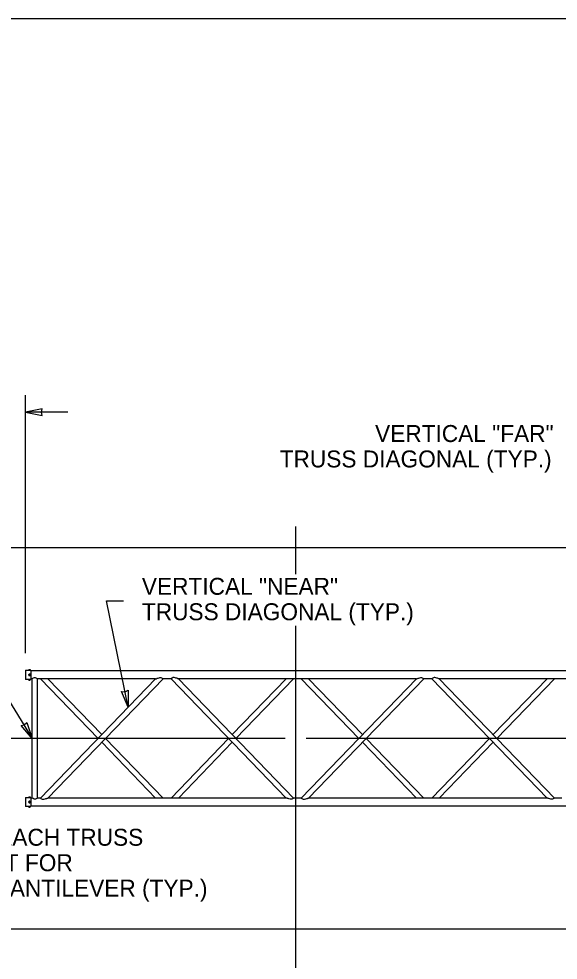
# Model space of a CAD drawing. Extents: x 99862 to 104211, y 98939 to 111076.
# Drawn here: x 100432 to 100941, y 104187 to 105075 of the extents above; entities that cross this region are included whole.
import ezdxf

# ---------------------------------------------------------------- set-up
doc = ezdxf.new("R2010")
doc.units = 0
for name, color, linetype in [('Level 15', 7, 'Continuous'), ('Level 20', 7, 'Continuous'), ('Level 6', 7, 'Continuous'), ('Level 60', 7, 'Continuous'), ('Level 62', 7, 'Continuous'), ('Level 9', 7, 'Continuous')]:
    doc.layers.add(name, color=color, linetype=linetype)

msp = doc.modelspace()

# ---------------------------------------------------------------- linework, layer by layer
at = {"layer": 'Level 15'}
for p, q in [((100438.11, 104476.27), (100438.11, 104719.89)), ((100478.11, 104703.89), (100438.11, 104703.89)), ((100301.12, 104629.04), (100444.36, 104395.89)), ((100693.11, 104595.89), (100693.11, 104550.99)), ((100534.96, 104425.29), (100514.64, 104525.79)), ((100514.64, 104525.79), (100530.64, 104525.79)), ((100693.11, 104502.01), (100693.11, 103988.28)), ((100683.11, 104395.89), (100213.11, 104395.89)), ((101294.5, 104395.89), (100703.11, 104395.89))]:
    msp.add_line(p, q, dxfattribs=at)
for points in [[(100438.11, 104703.89), (100453.84, 104700.81), (100453.11, 104703.89), (100453.84, 104706.98)], [(100534.96, 104425.29), (100528.82, 104440.09), (100531.99, 104439.99), (100534.87, 104441.32)], [(100444.36, 104395.89), (100433.83, 104407.97), (100436.87, 104408.88), (100439.17, 104411.05)]]:
    msp.add_lwpolyline(points, close=True, dxfattribs=at)
at = {"layer": 'Level 20'}
for p, q in [((100506.53, 104395.89), (100452.13, 104452.14)), ((100510.01, 104399.49), (100459.09, 104452.14)), ((100633.32, 104399.49), (100684.24, 104452.14)), ((100636.8, 104395.89), (100691.2, 104452.14)), ((100752.77, 104395.89), (100698.37, 104452.14)), ((100756.25, 104399.49), (100705.33, 104452.14)), ((100879.56, 104399.49), (100930.48, 104452.14)), ((100883.04, 104395.89), (100937.44, 104452.14)), ((100560.93, 104339.64), (100510.01, 104392.3)), ((100567.88, 104339.64), (100513.49, 104395.89)), ((100575.45, 104339.64), (100629.85, 104395.89)), ((100582.4, 104339.64), (100633.32, 104392.3)), ((100807.17, 104339.64), (100756.25, 104392.3)), ((100814.12, 104339.64), (100759.72, 104395.89)), ((100821.69, 104339.64), (100876.08, 104395.89)), ((100828.64, 104339.64), (100879.56, 104392.3))]:
    msp.add_line(p, q, dxfattribs=at)
at = {"layer": 'Level 6'}
for p, q in [((100985.61, 104575.89), (100400.61, 104575.89)), ((100438.11, 104460.27), (100438.11, 104451.52)), ((100438.11, 104460.27), (100441.16, 104460.27)), ((100442.57, 104460.27), (100443.11, 104460.27)), ((100443.11, 104460.27), (100443.11, 104451.52)), ((101326.12, 104459.64), (100443.11, 104459.64)), ((100441.16, 104451.52), (100438.11, 104451.52)), ((100443.11, 104451.52), (100442.57, 104451.52)), ((100444.36, 104452.14), (100443.11, 104452.14)), ((100444.36, 104339.64), (100444.36, 104452.14)), ((100449.36, 104339.64), (100449.36, 104452.14)), ((100560.93, 104452.14), (100449.36, 104452.14)), ((100449.36, 104339.64), (100449.36, 104452.13)), ((100560.93, 104452.14), (100452.13, 104339.64)), ((100567.88, 104452.14), (100459.09, 104339.64)), ((100575.45, 104452.14), (100567.88, 104452.14)), ((100575.45, 104452.14), (100684.24, 104339.64)), ((100582.4, 104452.14), (100691.2, 104339.64)), ((100807.17, 104452.14), (100582.4, 104452.14)), ((100807.17, 104452.14), (100698.37, 104339.64)), ((100814.12, 104452.14), (100705.33, 104339.64)), ((100821.69, 104452.14), (100814.12, 104452.14)), ((100821.69, 104452.14), (100930.48, 104339.64)), ((100828.64, 104452.14), (100937.44, 104339.64)), ((101053.4, 104452.14), (100828.64, 104452.14)), ((100438.11, 104340.27), (100438.11, 104331.52)), ((100438.11, 104340.27), (100441.16, 104340.27)), ((100442.57, 104340.27), (100443.11, 104340.27)), ((100443.11, 104340.27), (100443.11, 104331.52)), ((100444.36, 104339.64), (100443.11, 104339.64)), ((100452.14, 104339.64), (100449.36, 104339.64)), ((100684.24, 104339.64), (100459.09, 104339.64)), ((100698.37, 104339.64), (100691.2, 104339.64)), ((100930.48, 104339.64), (100705.33, 104339.64)), ((100944.61, 104339.64), (100937.43, 104339.64)), ((100441.16, 104331.52), (100438.11, 104331.52)), ((100443.11, 104331.52), (100442.57, 104331.52)), ((101326.12, 104332.14), (100443.11, 104332.14)), ((100985.61, 104215.89), (100400.61, 104215.89))]:
    msp.add_line(p, q, dxfattribs=at)
for points, degree in [([(100441.4, 104460.27), (100441.4, 104460.27), (100441.4, 104460.27), (100441.41, 104460.27), (100441.42, 104460.26), (100441.44, 104460.26), (100441.47, 104460.26), (100441.5, 104460.26), (100441.53, 104460.25), (100441.57, 104460.25), (100441.61, 104460.25), (100441.66, 104460.25), (100441.71, 104460.24), (100441.76, 104460.24), (100441.81, 104460.24), (100441.87, 104460.24), (100441.92, 104460.24), (100441.97, 104460.24), (100442.02, 104460.24), (100442.07, 104460.25), (100442.12, 104460.25), (100442.16, 104460.25), (100442.2, 104460.25), (100442.23, 104460.26), (100442.26, 104460.26), (100442.29, 104460.26), (100442.31, 104460.26), (100442.32, 104460.27), (100442.33, 104460.27), (100442.33, 104460.27), (100442.33, 104460.27)], 3), ([(100449.36, 104452.14), (100449.39, 104451.99), (100447.71, 104453.8), (100444.7, 104452.57), (100444.44, 104452.13), (100444.37, 104452.15), (100444.37, 104452.14), (100444.36, 104452.14)], 3), ([(100560.93, 104452.14), (100560.94, 104452.15), (100562.16, 104452.53), (100566.09, 104453.79), (100568, 104452.08), (100567.86, 104452.15), (100567.88, 104452.14)], 3), ([(100582.4, 104452.14), (100582.39, 104452.15), (100581.17, 104452.53), (100577.24, 104453.79), (100575.33, 104452.08), (100575.47, 104452.15), (100575.45, 104452.14)], 3), ([(100807.17, 104452.14), (100807.18, 104452.15), (100808.4, 104452.53), (100812.33, 104453.79), (100814.24, 104452.08), (100814.1, 104452.15), (100814.12, 104452.14)], 3), ([(100828.64, 104452.14), (100828.63, 104452.15), (100827.41, 104452.53), (100823.48, 104453.79), (100821.57, 104452.08), (100821.71, 104452.15), (100821.69, 104452.14)], 3), ([(100442.33, 104451.52), (100442.33, 104451.52), (100442.32, 104451.52), (100442.31, 104451.52), (100442.29, 104451.52), (100442.26, 104451.52), (100442.23, 104451.53), (100442.2, 104451.53), (100442.16, 104451.53), (100442.11, 104451.53), (100442.07, 104451.54), (100442.02, 104451.54), (100441.97, 104451.54), (100441.92, 104451.54), (100441.86, 104451.54), (100441.81, 104451.54), (100441.76, 104451.54), (100441.71, 104451.54), (100441.66, 104451.54), (100441.61, 104451.53), (100441.57, 104451.53), (100441.53, 104451.53), (100441.5, 104451.53), (100441.47, 104451.52), (100441.44, 104451.52), (100441.42, 104451.52), (100441.4, 104451.52), (100441.4, 104451.52), (100441.4, 104451.52), (100441.4, 104451.52), (100441.4, 104451.52)], 3), ([(100444.36, 104452.14), (100444.38, 104452.13), (100444.39, 104452.13), (100444.4, 104452.14)], 2), ([(100449.34, 104452.17), (100449.35, 104452.16), (100449.36, 104452.14), (100449.36, 104452.14), (100449.36, 104452.14)], 3), ([(100452.13, 104452.14), (100452.13, 104452.14), (100452.13, 104452.14), (100452.13, 104452.14)], 2), ([(100567.88, 104452.14), (100567.89, 104452.14), (100567.89, 104452.14), (100567.89, 104452.15)], 2), ([(100575.45, 104452.14), (100575.44, 104452.14), (100575.44, 104452.14), (100575.44, 104452.15)], 2), ([(100691.2, 104452.14), (100691.2, 104452.14), (100691.2, 104452.14), (100691.2, 104452.14)], 2), ([(100691.2, 104452.14), (100691.2, 104452.14), (100691.2, 104452.14), (100691.21, 104452.14)], 2), ([(100698.37, 104452.14), (100698.37, 104452.14), (100698.37, 104452.14), (100698.36, 104452.14)], 2), ([(100698.37, 104452.14), (100698.37, 104452.14), (100698.37, 104452.14), (100698.37, 104452.14)], 2), ([(100814.12, 104452.14), (100814.13, 104452.14), (100814.13, 104452.14), (100814.13, 104452.15)], 2), ([(100821.69, 104452.14), (100821.68, 104452.14), (100821.68, 104452.14), (100821.68, 104452.15)], 2), ([(100937.43, 104452.14), (100937.44, 104452.14), (100937.44, 104452.14), (100937.44, 104452.14)], 2), ([(100937.44, 104452.14), (100937.44, 104452.14), (100937.44, 104452.14), (100937.44, 104452.14)], 2), ([(100441.4, 104340.27), (100441.4, 104340.27), (100441.4, 104340.27), (100441.41, 104340.27), (100441.42, 104340.26), (100441.44, 104340.26), (100441.47, 104340.26), (100441.5, 104340.26), (100441.53, 104340.25), (100441.57, 104340.25), (100441.61, 104340.25), (100441.66, 104340.25), (100441.71, 104340.24), (100441.76, 104340.24), (100441.81, 104340.24), (100441.87, 104340.24), (100441.92, 104340.24), (100441.97, 104340.24), (100442.02, 104340.24), (100442.07, 104340.25), (100442.12, 104340.25), (100442.16, 104340.25), (100442.2, 104340.25), (100442.23, 104340.26), (100442.26, 104340.26), (100442.29, 104340.26), (100442.31, 104340.26), (100442.32, 104340.27), (100442.33, 104340.27), (100442.33, 104340.27), (100442.33, 104340.27)], 3), ([(100449.36, 104339.64), (100449.39, 104339.8), (100447.71, 104337.98), (100444.7, 104339.21), (100444.44, 104339.65), (100444.37, 104339.64), (100444.37, 104339.64), (100444.36, 104339.64)], 3), ([(100444.36, 104339.64), (100444.38, 104339.65), (100444.39, 104339.65), (100444.4, 104339.64)], 2), ([(100449.34, 104339.62), (100449.35, 104339.62), (100449.36, 104339.64), (100449.36, 104339.64), (100449.36, 104339.64)], 3), ([(100452.13, 104339.64), (100452, 104339.66), (100453.92, 104338.13), (100456.83, 104339), (100458.02, 104339.3), (100458.33, 104339.4), (100458.57, 104339.48), (100458.77, 104339.54), (100458.93, 104339.59), (100459.04, 104339.62), (100459.08, 104339.64), (100459.09, 104339.64), (100459.09, 104339.64), (100459.09, 104339.64)], 3), ([(100452.14, 104339.64), (100452.13, 104339.64), (100452.13, 104339.64), (100452.13, 104339.64)], 2), ([(100459.09, 104339.64), (100459.09, 104339.64), (100459.09, 104339.64), (100459.09, 104339.64)], 2), ([(100691.2, 104339.64), (100691.33, 104339.66), (100689.41, 104338.13), (100686.5, 104339), (100685.31, 104339.3), (100685, 104339.4), (100684.76, 104339.48), (100684.56, 104339.54), (100684.4, 104339.59), (100684.29, 104339.62), (100684.25, 104339.64), (100684.24, 104339.64), (100684.24, 104339.64), (100684.24, 104339.64)], 3), ([(100684.24, 104339.64), (100684.24, 104339.64), (100684.24, 104339.64), (100684.25, 104339.64)], 2), ([(100691.2, 104339.64), (100691.2, 104339.64), (100691.2, 104339.64), (100691.2, 104339.64)], 2), ([(100698.37, 104339.64), (100698.24, 104339.66), (100700.16, 104338.13), (100703.07, 104339), (100704.26, 104339.3), (100704.56, 104339.4), (100704.81, 104339.48), (100705.01, 104339.54), (100705.17, 104339.59), (100705.27, 104339.62), (100705.32, 104339.64), (100705.33, 104339.64), (100705.33, 104339.64), (100705.33, 104339.64)], 3), ([(100698.37, 104339.64), (100698.37, 104339.64), (100698.37, 104339.64), (100698.37, 104339.64)], 2), ([(100705.33, 104339.64), (100705.33, 104339.64), (100705.32, 104339.64), (100705.32, 104339.64)], 2), ([(100937.44, 104339.64), (100937.57, 104339.66), (100935.65, 104338.13), (100932.74, 104339), (100931.55, 104339.3), (100931.24, 104339.4), (100931, 104339.48), (100930.8, 104339.54), (100930.64, 104339.59), (100930.53, 104339.62), (100930.49, 104339.64), (100930.48, 104339.64), (100930.48, 104339.64), (100930.48, 104339.64)], 3), ([(100930.48, 104339.64), (100930.48, 104339.64), (100930.48, 104339.64), (100930.48, 104339.64)], 2), ([(100937.43, 104339.64), (100937.44, 104339.64), (100937.44, 104339.64), (100937.44, 104339.64)], 2), ([(100442.33, 104331.52), (100442.33, 104331.52), (100442.32, 104331.52), (100442.31, 104331.52), (100442.29, 104331.52), (100442.26, 104331.52), (100442.23, 104331.53), (100442.2, 104331.53), (100442.16, 104331.53), (100442.11, 104331.53), (100442.07, 104331.54), (100442.02, 104331.54), (100441.97, 104331.54), (100441.92, 104331.54), (100441.86, 104331.54), (100441.81, 104331.54), (100441.76, 104331.54), (100441.71, 104331.54), (100441.66, 104331.54), (100441.61, 104331.53), (100441.57, 104331.53), (100441.53, 104331.53), (100441.5, 104331.53), (100441.47, 104331.52), (100441.44, 104331.52), (100441.42, 104331.52), (100441.4, 104331.52), (100441.4, 104331.52), (100441.4, 104331.52), (100441.4, 104331.52), (100441.4, 104331.52)], 3)]:
    msp.add_open_spline(points, degree=degree, dxfattribs=at)
at = {"layer": 'Level 60'}
msp.add_line((103150, 105075), (100000, 105075), dxfattribs=at)
at = {"layer": 'Level 62'}
for points in [[(100441.86, 104451.52), (100441.74, 104451.52), (100441.61, 104451.52), (100441.53, 104451.53)], [(100441.86, 104331.52), (100441.74, 104331.52), (100441.61, 104331.52), (100441.53, 104331.53)]]:
    msp.add_open_spline(points, degree=2, dxfattribs=at)
at = {"layer": 'Level 9'}
for p, q in [((100441.16, 104460.89), (100441.5, 104460.89)), ((100441.16, 104460.83), (100441.16, 104460.27)), ((100441.16, 104460.27), (100441.86, 104460.27)), ((100441.5, 104460.89), (100441.53, 104460.89)), ((100441.5, 104455.29), (100441.53, 104455.28)), ((100441.53, 104460.89), (100442.2, 104460.89)), ((100441.86, 104460.83), (100441.86, 104460.27)), ((100441.86, 104460.27), (100442.57, 104460.27)), ((100442.2, 104460.89), (100442.23, 104460.89)), ((100442.2, 104455.27), (100442.23, 104455.29)), ((100442.22, 104456.5), (100442.21, 104456.51)), ((100442.23, 104460.89), (100442.57, 104460.89)), ((100442.57, 104460.83), (100442.57, 104460.27)), ((100442.57, 104455.87), (100442.57, 104455.91)), ((100441.16, 104450.95), (100441.16, 104451.52)), ((100441.86, 104451.52), (100441.16, 104451.52)), ((100441.16, 104450.89), (100442.21, 104450.89)), ((100442.57, 104451.52), (100441.86, 104451.52)), ((100441.86, 104450.95), (100441.86, 104451.52)), ((100442.22, 104450.89), (100442.21, 104450.89)), ((100442.22, 104450.89), (100442.57, 104450.89)), ((100442.57, 104450.95), (100442.57, 104451.52)), ((100441.16, 104340.89), (100441.5, 104340.89)), ((100441.16, 104340.83), (100441.16, 104340.27)), ((100441.16, 104340.27), (100441.86, 104340.27)), ((100441.5, 104340.89), (100441.53, 104340.89)), ((100441.53, 104340.89), (100442.2, 104340.89)), ((100441.86, 104340.83), (100441.86, 104340.27)), ((100441.86, 104340.27), (100442.57, 104340.27)), ((100442.2, 104340.89), (100442.23, 104340.89)), ((100442.23, 104340.89), (100442.57, 104340.89)), ((100442.57, 104340.83), (100442.57, 104340.27)), ((100441.86, 104331.52), (100441.16, 104331.52)), ((100441.16, 104330.95), (100441.16, 104331.52)), ((100441.16, 104330.89), (100442.21, 104330.89)), ((100441.5, 104335.29), (100441.53, 104335.28)), ((100442.57, 104331.52), (100441.86, 104331.52)), ((100441.86, 104330.95), (100441.86, 104331.52)), ((100442.2, 104335.27), (100442.23, 104335.29)), ((100442.22, 104336.5), (100442.21, 104336.51)), ((100442.22, 104330.89), (100442.21, 104330.89)), ((100442.22, 104330.89), (100442.57, 104330.89)), ((100442.57, 104335.87), (100442.57, 104335.91)), ((100442.57, 104330.95), (100442.57, 104331.52))]:
    msp.add_line(p, q, dxfattribs=at)
for centre, start, end in [((100441.86, 104455.89), 60.75538, 180), ((100441.86, 104455.89), 180, 238.8031), ((100441.86, 104455.89), 241.1969, 298.43917), ((100441.86, 104455.89), 1.41676, 59.24201), ((100441.86, 104455.89), 301.56083, 358.58324), ((100441.86, 104335.89), 60.75538, 180), ((100441.86, 104335.89), 180, 238.8031), ((100441.86, 104335.89), 241.1969, 298.43917), ((100441.86, 104335.89), 1.41676, 59.24201), ((100441.86, 104335.89), 301.56083, 358.58324)]:
    msp.add_arc(centre, 0.703, start, end, dxfattribs=at)
for points, degree in [([(100441.16, 104460.89), (100441.16, 104460.89), (100441.16, 104460.89), (100441.16, 104460.89), (100441.16, 104460.88), (100441.16, 104460.86), (100441.16, 104460.83)], 3), ([(100441.16, 104460.83), (100441.16, 104460.84), (100441.16, 104460.85), (100441.16, 104460.85), (100441.16, 104460.88), (100441.16, 104460.89), (100441.16, 104460.89)], 3), ([(100441.16, 104460.83), (100441.27, 104460.87), (100441.39, 104460.89), (100441.5, 104460.89)], 2), ([(100441.86, 104456.7), (100441.74, 104456.63), (100441.62, 104456.56), (100441.49, 104456.49), (100441.38, 104456.42), (100441.27, 104456.36), (100441.16, 104456.3)], 3), ([(100441.16, 104455.89), (100441.16, 104455.93), (100441.16, 104455.96), (100441.16, 104456), (100441.16, 104456.1), (100441.16, 104456.2), (100441.16, 104456.3)], 3), ([(100441.16, 104455.49), (100441.16, 104455.52), (100441.16, 104455.55), (100441.16, 104455.58), (100441.16, 104455.68), (100441.16, 104455.79), (100441.16, 104455.89)], 3), ([(100441.16, 104455.49), (100441.27, 104455.42), (100441.39, 104455.36), (100441.5, 104455.29)], 2), ([(100441.53, 104460.89), (100441.53, 104460.89), (100441.53, 104460.89), (100441.54, 104460.89), (100441.65, 104460.89), (100441.76, 104460.86), (100441.86, 104460.83)], 3), ([(100441.53, 104455.28), (100441.53, 104455.27), (100441.53, 104455.27), (100441.54, 104455.27), (100441.65, 104455.21), (100441.76, 104455.14), (100441.86, 104455.08)], 3), ([(100441.86, 104460.83), (100441.97, 104460.87), (100442.09, 104460.89), (100442.2, 104460.89)], 2), ([(100442.21, 104456.51), (100442.2, 104456.51), (100442.2, 104456.51), (100442.19, 104456.51), (100442.08, 104456.58), (100441.97, 104456.64), (100441.86, 104456.7)], 3), ([(100441.86, 104455.08), (100441.97, 104455.14), (100442.09, 104455.21), (100442.2, 104455.27)], 2), ([(100442.57, 104456.3), (100442.46, 104456.36), (100442.34, 104456.43), (100442.22, 104456.5)], 2), ([(100442.23, 104460.89), (100442.24, 104460.89), (100442.24, 104460.89), (100442.24, 104460.89), (100442.35, 104460.89), (100442.46, 104460.86), (100442.57, 104460.83)], 3), ([(100442.23, 104455.29), (100442.24, 104455.29), (100442.24, 104455.3), (100442.24, 104455.3), (100442.35, 104455.36), (100442.46, 104455.42), (100442.57, 104455.49)], 3), ([(100442.57, 104460.89), (100442.57, 104460.89), (100442.57, 104460.89), (100442.57, 104460.89), (100442.57, 104460.88), (100442.57, 104460.86), (100442.57, 104460.83)], 3), ([(100442.57, 104460.83), (100442.57, 104460.84), (100442.57, 104460.85), (100442.57, 104460.85), (100442.57, 104460.88), (100442.57, 104460.89), (100442.57, 104460.89)], 3), ([(100442.57, 104455.91), (100442.57, 104455.94), (100442.57, 104455.97), (100442.57, 104456), (100442.57, 104456.1), (100442.57, 104456.2), (100442.57, 104456.3)], 3), ([(100442.57, 104455.49), (100442.57, 104455.52), (100442.57, 104455.55), (100442.57, 104455.58), (100442.57, 104455.68), (100442.57, 104455.78), (100442.57, 104455.87)], 3), ([(100441.16, 104450.95), (100441.16, 104450.95), (100441.16, 104450.94), (100441.16, 104450.93), (100441.16, 104450.91), (100441.16, 104450.89), (100441.16, 104450.89)], 3), ([(100441.16, 104450.89), (100441.16, 104450.89), (100441.16, 104450.89), (100441.16, 104450.9), (100441.16, 104450.9), (100441.16, 104450.93), (100441.16, 104450.95)], 3), ([(100441.86, 104450.95), (100441.74, 104450.91), (100441.62, 104450.89), (100441.49, 104450.89), (100441.38, 104450.89), (100441.27, 104450.92), (100441.16, 104450.95)], 3), ([(100441.53, 104450.89), (100441.53, 104450.89), (100441.53, 104450.89), (100441.53, 104450.89)], 2), ([(100442.21, 104450.89), (100442.2, 104450.89), (100442.2, 104450.89), (100442.19, 104450.89), (100442.08, 104450.89), (100441.97, 104450.92), (100441.86, 104450.95)], 3), ([(100442.57, 104450.95), (100442.46, 104450.92), (100442.34, 104450.89), (100442.22, 104450.89)], 2), ([(100442.57, 104450.95), (100442.57, 104450.95), (100442.57, 104450.94), (100442.57, 104450.93), (100442.57, 104450.91), (100442.57, 104450.89), (100442.57, 104450.89)], 3), ([(100442.57, 104450.89), (100442.57, 104450.89), (100442.57, 104450.89), (100442.57, 104450.9), (100442.57, 104450.9), (100442.57, 104450.93), (100442.57, 104450.95)], 3), ([(100441.16, 104340.89), (100441.16, 104340.89), (100441.16, 104340.89), (100441.16, 104340.89), (100441.16, 104340.88), (100441.16, 104340.86), (100441.16, 104340.83)], 3), ([(100441.16, 104340.83), (100441.16, 104340.84), (100441.16, 104340.85), (100441.16, 104340.85), (100441.16, 104340.88), (100441.16, 104340.89), (100441.16, 104340.89)], 3), ([(100441.16, 104340.83), (100441.27, 104340.87), (100441.39, 104340.89), (100441.5, 104340.89)], 2), ([(100441.53, 104340.89), (100441.53, 104340.89), (100441.53, 104340.89), (100441.54, 104340.89), (100441.65, 104340.89), (100441.76, 104340.86), (100441.86, 104340.83)], 3), ([(100441.86, 104340.83), (100441.97, 104340.87), (100442.09, 104340.89), (100442.2, 104340.89)], 2), ([(100442.23, 104340.89), (100442.24, 104340.89), (100442.24, 104340.89), (100442.24, 104340.89), (100442.35, 104340.89), (100442.46, 104340.86), (100442.57, 104340.83)], 3), ([(100442.57, 104340.89), (100442.57, 104340.89), (100442.57, 104340.89), (100442.57, 104340.89), (100442.57, 104340.88), (100442.57, 104340.86), (100442.57, 104340.83)], 3), ([(100442.57, 104340.83), (100442.57, 104340.84), (100442.57, 104340.85), (100442.57, 104340.85), (100442.57, 104340.88), (100442.57, 104340.89), (100442.57, 104340.89)], 3), ([(100441.86, 104336.7), (100441.74, 104336.63), (100441.62, 104336.56), (100441.49, 104336.49), (100441.38, 104336.42), (100441.27, 104336.36), (100441.16, 104336.3)], 3), ([(100441.16, 104335.89), (100441.16, 104335.93), (100441.16, 104335.96), (100441.16, 104336), (100441.16, 104336.1), (100441.16, 104336.2), (100441.16, 104336.3)], 3), ([(100441.16, 104335.49), (100441.16, 104335.52), (100441.16, 104335.55), (100441.16, 104335.58), (100441.16, 104335.68), (100441.16, 104335.79), (100441.16, 104335.89)], 3), ([(100441.16, 104335.49), (100441.27, 104335.42), (100441.39, 104335.36), (100441.5, 104335.29)], 2), ([(100441.16, 104330.95), (100441.16, 104330.95), (100441.16, 104330.94), (100441.16, 104330.93), (100441.16, 104330.91), (100441.16, 104330.89), (100441.16, 104330.89)], 3), ([(100441.16, 104330.89), (100441.16, 104330.89), (100441.16, 104330.89), (100441.16, 104330.9), (100441.16, 104330.9), (100441.16, 104330.93), (100441.16, 104330.95)], 3), ([(100441.86, 104330.95), (100441.74, 104330.91), (100441.62, 104330.89), (100441.49, 104330.89), (100441.38, 104330.89), (100441.27, 104330.92), (100441.16, 104330.95)], 3), ([(100441.53, 104335.28), (100441.53, 104335.27), (100441.53, 104335.27), (100441.54, 104335.27), (100441.65, 104335.21), (100441.76, 104335.14), (100441.86, 104335.08)], 3), ([(100441.53, 104330.89), (100441.53, 104330.89), (100441.53, 104330.89), (100441.53, 104330.89)], 2), ([(100442.21, 104336.51), (100442.2, 104336.51), (100442.2, 104336.51), (100442.19, 104336.51), (100442.08, 104336.58), (100441.97, 104336.64), (100441.86, 104336.7)], 3), ([(100441.86, 104335.08), (100441.97, 104335.14), (100442.09, 104335.21), (100442.2, 104335.27)], 2), ([(100442.21, 104330.89), (100442.2, 104330.89), (100442.2, 104330.89), (100442.19, 104330.89), (100442.08, 104330.89), (100441.97, 104330.92), (100441.86, 104330.95)], 3), ([(100442.57, 104336.3), (100442.46, 104336.36), (100442.34, 104336.43), (100442.22, 104336.5)], 2), ([(100442.57, 104330.95), (100442.46, 104330.92), (100442.34, 104330.89), (100442.22, 104330.89)], 2), ([(100442.23, 104335.29), (100442.24, 104335.29), (100442.24, 104335.3), (100442.24, 104335.3), (100442.35, 104335.36), (100442.46, 104335.42), (100442.57, 104335.49)], 3), ([(100442.57, 104335.91), (100442.57, 104335.94), (100442.57, 104335.97), (100442.57, 104336), (100442.57, 104336.1), (100442.57, 104336.2), (100442.57, 104336.3)], 3), ([(100442.57, 104335.49), (100442.57, 104335.52), (100442.57, 104335.55), (100442.57, 104335.58), (100442.57, 104335.68), (100442.57, 104335.78), (100442.57, 104335.87)], 3), ([(100442.57, 104330.95), (100442.57, 104330.95), (100442.57, 104330.94), (100442.57, 104330.93), (100442.57, 104330.91), (100442.57, 104330.89), (100442.57, 104330.89)], 3), ([(100442.57, 104330.89), (100442.57, 104330.89), (100442.57, 104330.89), (100442.57, 104330.9), (100442.57, 104330.9), (100442.57, 104330.93), (100442.57, 104330.95)], 3)]:
    msp.add_open_spline(points, degree=degree, dxfattribs=at)

# ---------------------------------------------------------------- texts
at = {"layer": 'Level 20'}
for s, p in [('VERTICAL "FAR"', (100768.14, 104675.65)), ('TRUSS DIAGONAL (TYP.)', (100678.06, 104651.65)), ('VERTICAL "NEAR"', (100547.93, 104531.45)), ('TRUSS DIAGONAL (TYP.)', (100547.93, 104507.45)), ('CAMBER EACH TRUSS', (100313.86, 104294.63)), ('0.002 FT/FT FOR ', (100313.86, 104270.63)), ('DOUBLE CANTILEVER (TYP.)', (100313.86, 104246.63))]:
    msp.add_text(s, height=16, rotation=360, dxfattribs=at).set_placement(p)

doc.saveas('drawing.dxf')
